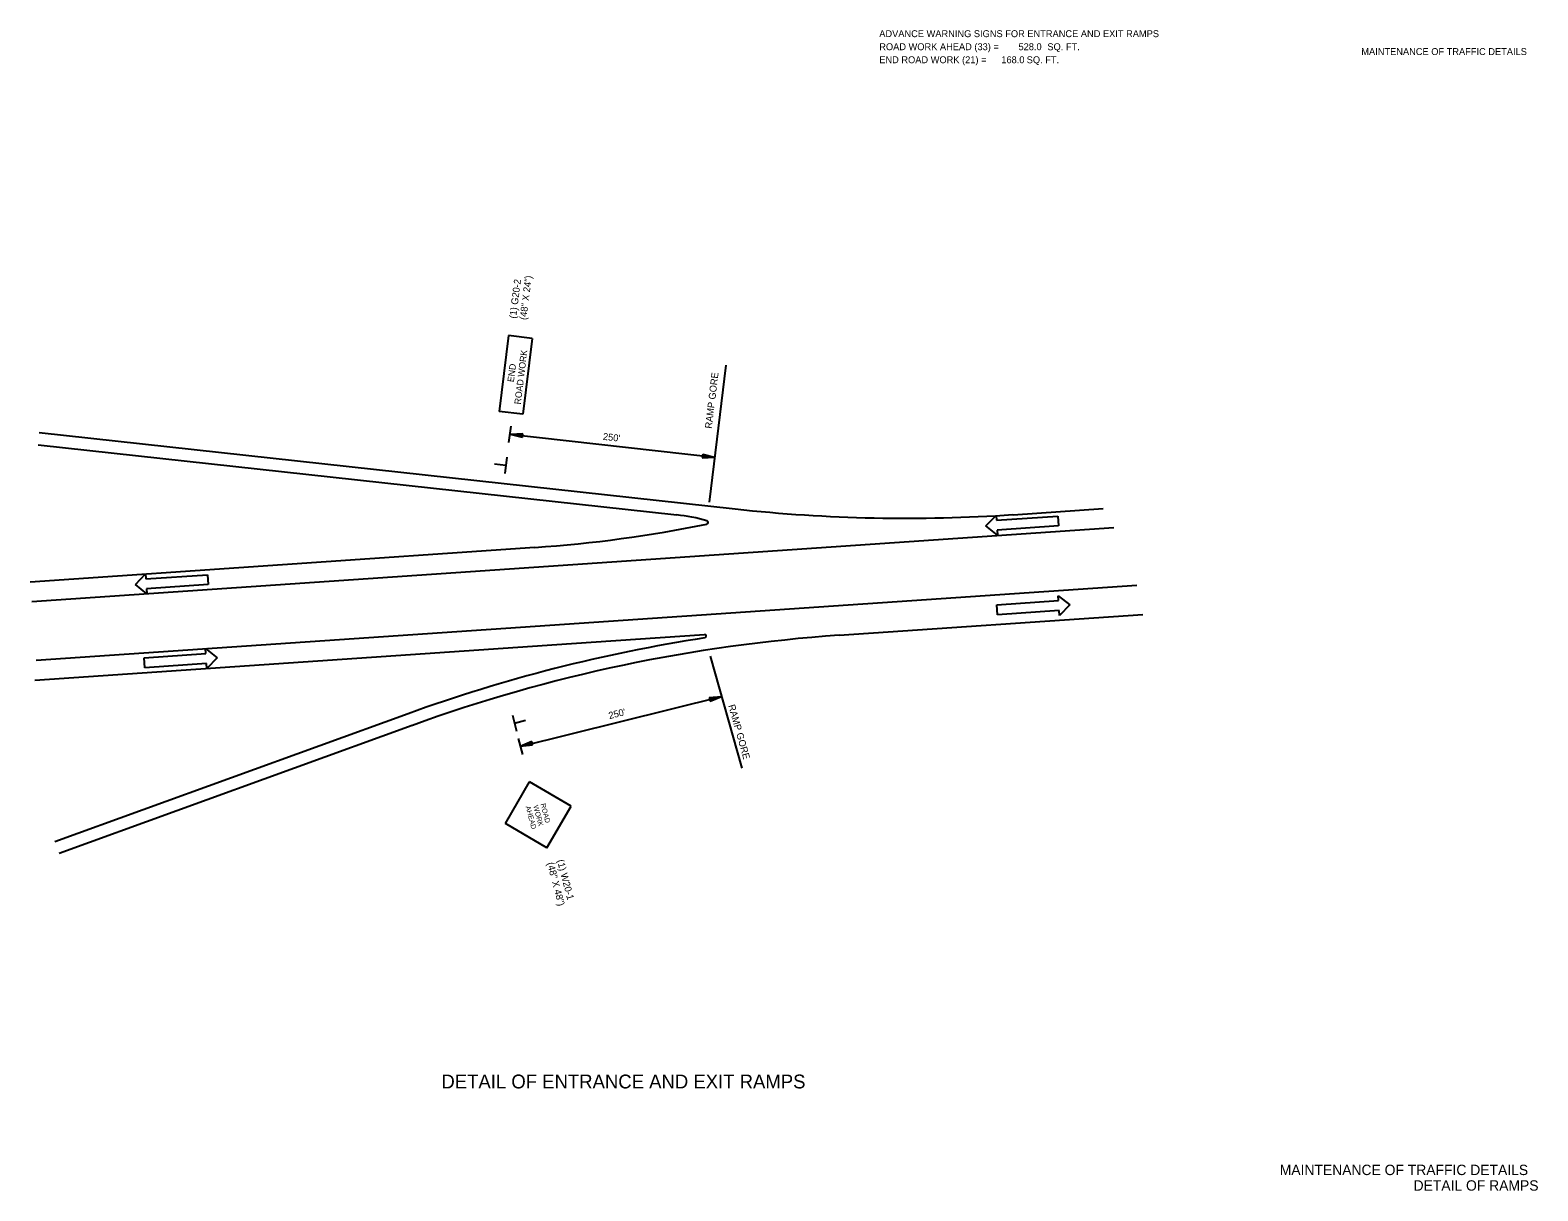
# Model space of a CAD drawing. Extents: x 1373848 to 1374003, y 380642 to 381248.
# Drawn here: x 1373872.2 to 1374002.9, y 380642.3 to 380742.9 of the extents above; entities that cross this region are included whole.
import ezdxf

# ---------------------------------------------------------------- set-up
doc = ezdxf.new("R2010")
doc.units = 0
for name, color, linetype in [('Default', 7, 'Continuous'), ('G-ANNO-TEXT', 7, 'Continuous'), ('R_Draft', 7, 'Continuous'), ('R_Exist Surface', 7, 'Continuous'), ('R_MOT', 7, 'Continuous')]:
    doc.layers.add(name, color=color, linetype=linetype)

msp = doc.modelspace()

# ---------------------------------------------------------------- linework, layer by layer
at = {"layer": 'R_Draft'}
for p, q in [((1373914.89, 380707.89), (1373913.82, 380707.85)), ((1373914.86, 380707.57), (1373913.82, 380707.85)), ((1373914.89, 380707.86), (1373914, 380707.83)), ((1373914.86, 380707.6), (1373914, 380707.83)), ((1373914.89, 380707.84), (1373914.18, 380707.81)), ((1373914.86, 380707.63), (1373914.18, 380707.81)), ((1373914.88, 380707.81), (1373914.35, 380707.79)), ((1373914.87, 380707.65), (1373914.35, 380707.79)), ((1373914.88, 380707.78), (1373914.53, 380707.77)), ((1373914.87, 380707.68), (1373914.53, 380707.77)), ((1373914.88, 380707.76), (1373914.71, 380707.75)), ((1373914.87, 380707.71), (1373914.71, 380707.75)), ((1373914.86, 380707.57), (1373914.89, 380707.89)), ((1373930.5, 380706.13), (1373930.46, 380705.82)), ((1373930.46, 380705.82), (1373931.53, 380705.86)), ((1373930.47, 380705.9), (1373931, 380705.92)), ((1373930.47, 380705.87), (1373931.18, 380705.9)), ((1373930.47, 380705.84), (1373931.36, 380705.87)), ((1373930.48, 380706), (1373930.65, 380705.95)), ((1373930.48, 380705.95), (1373930.65, 380705.95)), ((1373930.48, 380705.92), (1373930.82, 380705.94)), ((1373930.49, 380706.08), (1373931.18, 380705.9)), ((1373930.49, 380706.05), (1373931, 380705.92)), ((1373930.49, 380706.02), (1373930.82, 380705.94)), ((1373930.5, 380706.13), (1373931.53, 380705.86)), ((1373930.5, 380706.11), (1373931.36, 380705.87)), ((1373931.05, 380685.04), (1373932.12, 380685.14)), ((1373931.05, 380685.04), (1373931.13, 380684.73)), ((1373931.06, 380685.01), (1373931.95, 380685.09)), ((1373931.07, 380684.98), (1373931.77, 380685.05)), ((1373931.07, 380684.96), (1373931.6, 380685.01)), ((1373931.08, 380684.93), (1373931.42, 380684.97)), ((1373931.08, 380684.91), (1373931.25, 380684.92)), ((1373931.1, 380684.83), (1373931.42, 380684.97)), ((1373931.1, 380684.86), (1373931.25, 380684.92)), ((1373931.11, 380684.81), (1373931.6, 380685.01)), ((1373931.12, 380684.75), (1373931.95, 380685.09)), ((1373931.12, 380684.78), (1373931.77, 380685.05)), ((1373931.13, 380684.73), (1373932.12, 380685.14)), ((1373915.67, 380681.22), (1373914.68, 380680.81)), ((1373915.75, 380680.91), (1373914.68, 380680.81)), ((1373915.68, 380681.19), (1373914.86, 380680.85)), ((1373915.74, 380680.93), (1373914.86, 380680.85)), ((1373915.69, 380681.16), (1373915.03, 380680.89)), ((1373915.74, 380680.96), (1373915.03, 380680.89)), ((1373915.69, 380681.14), (1373915.2, 380680.94)), ((1373915.73, 380680.99), (1373915.2, 380680.94)), ((1373915.7, 380681.11), (1373915.38, 380680.98)), ((1373915.72, 380681.01), (1373915.38, 380680.98)), ((1373915.71, 380681.09), (1373915.55, 380681.02)), ((1373915.72, 380681.04), (1373915.55, 380681.02)), ((1373915.75, 380680.91), (1373915.67, 380681.22))]:
    msp.add_line(p, q, dxfattribs=at)
at = {"layer": 'R_Exist Surface'}
for p, q in [((1373872.97, 380708.01), (1373933.32, 380701.39)), ((1373872.88, 380706.94), (1373928.24, 380700.87)), ((1373957.4, 380700.89), (1373965.21, 380701.42)), ((1373872.33, 380693.37), (1373966.14, 380699.78)), ((1373872.19, 380695.08), (1373915.94, 380698.06)), ((1373872.71, 380688.27), (1373968.14, 380694.78)), ((1373942.33, 380690.44), (1373968.64, 380692.24)), ((1373919.13, 380689.72), (1373930.64, 380690.51)), ((1373872.59, 380686.55), (1373919.13, 380689.72)), ((1373874.34, 380672.56), (1373904.96, 380683.65)), ((1373874.71, 380671.55), (1373905.32, 380682.64))]:
    msp.add_line(p, q, dxfattribs=at)
for centre, radius, start, end in [((1373948.15, 380836.46), 135.88, 263.7335, 273.9), ((1373908.38, 380809.92), 112.12, 273.8643, 281.5623), ((1373926.62, 380685.42), 15.53, 74.1458, 84.0343), ((1373930.83, 380700.22), 0.143, 281.6258, 73.5312), ((1373930.65, 380690.36), 0.143, 278.7808, 93.9002), ((1373951.58, 380554.87), 136.95, 98.7808, 109.9033), ((1373951.58, 380554.87), 135.88, 93.9033, 109.9033)]:
    msp.add_arc(centre, radius, start, end, dxfattribs=at)
at = {"layer": 'R_MOT'}
for p, q in [((1373913.65, 380716.42), (1373912.85, 380709.84)), ((1373915.72, 380716.17), (1373913.65, 380716.42)), ((1373915.72, 380716.17), (1373914.91, 380709.59)), ((1373932.5, 380713.85), (1373931.06, 380701.96)), ((1373914.91, 380709.59), (1373912.85, 380709.84)), ((1373913.85, 380708.56), (1373913.67, 380707.15)), ((1373913.76, 380707.86), (1373931.53, 380705.86)), ((1373913.43, 380705.16), (1373912.45, 380705.27)), ((1373913.51, 380705.86), (1373913.35, 380704.45)), ((1373955.04, 380699.91), (1373955.92, 380700.83)), ((1373956.04, 380699.12), (1373955.04, 380699.91)), ((1373955.92, 380700.83), (1373955.95, 380700.4)), ((1373955.95, 380700.4), (1373961.29, 380700.76)), ((1373961.35, 380699.91), (1373956.01, 380699.54)), ((1373961.29, 380700.76), (1373961.35, 380699.91)), ((1373956.01, 380699.54), (1373956.04, 380699.12)), ((1373881.32, 380694.83), (1373882.2, 380695.75)), ((1373882.2, 380695.75), (1373882.23, 380695.32)), ((1373882.31, 380694.04), (1373881.32, 380694.83)), ((1373882.23, 380695.32), (1373887.57, 380695.69)), ((1373887.62, 380694.83), (1373882.28, 380694.47)), ((1373882.28, 380694.47), (1373882.31, 380694.04)), ((1373887.57, 380695.69), (1373887.62, 380694.83)), ((1373956, 380693.07), (1373961.34, 380693.44)), ((1373961.34, 380693.44), (1373961.31, 380693.87)), ((1373961.31, 380693.87), (1373962.31, 380693.07)), ((1373956.06, 380692.22), (1373956, 380693.07)), ((1373961.4, 380692.58), (1373956.06, 380692.22)), ((1373961.43, 380692.15), (1373961.4, 380692.58)), ((1373962.31, 380693.07), (1373961.43, 380692.15)), ((1373887.42, 380688.85), (1373887.39, 380689.28)), ((1373887.39, 380689.28), (1373888.39, 380688.49)), ((1373882.08, 380688.49), (1373887.42, 380688.85)), ((1373882.14, 380687.63), (1373882.08, 380688.49)), ((1373887.48, 380688), (1373882.14, 380687.63)), ((1373887.51, 380687.57), (1373887.48, 380688)), ((1373888.39, 380688.49), (1373887.51, 380687.57)), ((1373931.13, 380688.64), (1373933.88, 380678.91)), ((1373914.68, 380680.81), (1373932.12, 380685.14)), ((1373913.99, 380683.51), (1373914.36, 380682.14)), ((1373914.17, 380682.83), (1373915.13, 380683.09)), ((1373914.5, 380681.5), (1373914.87, 380680.12)), ((1373913.39, 380674.13), (1373915.49, 380677.73)), ((1373919.09, 380675.63), (1373915.49, 380677.73)), ((1373916.98, 380672.03), (1373919.09, 380675.63)), ((1373916.98, 380672.03), (1373913.39, 380674.13))]:
    msp.add_line(p, q, dxfattribs=at)

# ---------------------------------------------------------------- texts
at = {"layer": 'Default'}
msp.add_text('DETAIL OF ENTRANCE AND EXIT RAMPS', height=1.2, dxfattribs=at).set_placement((1373907.84, 380651.17))
at = {"layer": 'G-ANNO-TEXT'}
for s, height, p in [('MAINTENANCE OF TRAFFIC DETAILS', 0.6, (1373987.59, 380740.72)), ('MAINTENANCE OF TRAFFIC DETAILS', 0.9, (1373980.52, 380643.66)), ('DETAIL OF RAMPS', 0.9, (1373992.12, 380642.31))]:
    msp.add_text(s, height=height, dxfattribs=at).set_placement(p)
at = {"layer": 'R_MOT'}
for s, p in [('ADVANCE WARNING SIGNS FOR ENTRANCE AND EXIT RAMPS', (1373945.8, 380742.27)), ('ROAD WORK AHEAD (33) = ', (1373945.8, 380741.14)), ('528.0', (1373957.87, 380741.14)), (' SQ. FT.', (1373960.15, 380741.14)), ('END ROAD WORK (21) = ', (1373945.8, 380740.01)), ('168.0', (1373956.38, 380740.01)), (' SQ. FT.', (1373958.36, 380740.01))]:
    msp.add_text(s, height=0.6, dxfattribs=at).set_placement(p)
for s, height, rotation, p in [('(1) G20-2', 0.599, 82.6881, (1373914.31, 380717.86)), ('(48" X 24")', 0.5988, 82.6881, (1373915.2, 380717.74)), ('ROAD WORK', 0.566, 82.996, (1373914.72, 380710.42)), ('END', 0.566, 82.996, (1373914.12, 380712.35)), ('RAMP GORE', 0.6, 83.096, (1373931.28, 380708.32)), ("250'", 0.6, 353.5767, (1373921.82, 380707.38)), ("250'", 0.6, 13.9505, (1373922.41, 380683.17)), ('RAMP GORE', 0.6, 285.8221, (1373932.7, 380684.35)), ('AHEAD', 0.434, 284.6842, (1373915.14, 380675.59)), ('WORK', 0.434, 284.6836, (1373915.8, 380675.65)), ('ROAD', 0.434, 284.6841, (1373916.43, 380675.81)), ('(1) W20-1', 0.603, 284.6836, (1373917.86, 380670.92)), ('(48" X 48")', 0.6031, 284.6836, (1373916.99, 380670.69))]:
    msp.add_text(s, height=height, rotation=rotation, dxfattribs=at).set_placement(p)

doc.saveas('drawing.dxf')
